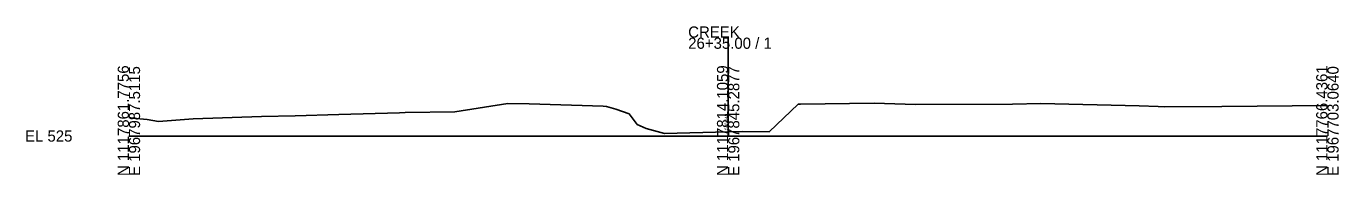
# Model space of a CAD drawing. Extents: x 9974 to 10303, y 9990 to 19550.
# Drawn here: x 9974.3 to 10302.8, y 15990.3 to 16027.5 of the extents above; entities that cross this region are included whole.
import ezdxf

# ---------------------------------------------------------------- set-up
doc = ezdxf.new("R2010")
doc.units = 0
for name, color, linetype in [('Level 10', 7, 'Continuous'), ('Level 60', 7, 'Continuous'), ('Level 63', 7, 'Continuous')]:
    doc.layers.add(name, color=color, linetype=linetype)

msp = doc.modelspace()

# ---------------------------------------------------------------- linework, layer by layer
at = {"layer": 'Level 60'}
for p, q in [((10081.57, 16006.09), (10094.84, 16008.14)), ((10094.84, 16008.14), (10100.16, 16008.06)), ((10100.16, 16008.06), (10118.7, 16007.45)), ((10118.7, 16007.45), (10119.51, 16007.42)), ((10119.51, 16007.42), (10121.91, 16006.75)), ((10121.91, 16006.75), (10125.23, 16005.56)), ((10160.27, 16001.03), (10167.54, 16007.95)), ((10167.54, 16007.95), (10168.11, 16007.96)), ((10168.11, 16007.96), (10186.51, 16008.21)), ((10186.51, 16008.21), (10196.87, 16007.9)), ((10196.87, 16007.9), (10221.21, 16007.98)), ((10221.21, 16007.98), (10228.26, 16008.15)), ((10228.26, 16008.15), (10252.85, 16007.53)), ((10252.85, 16007.53), (10257.66, 16007.36)), ((10257.66, 16007.36), (10259.1, 16007.33)), ((10259.1, 16007.33), (10273.54, 16007.4)), ((10273.54, 16007.4), (10300, 16007.61)), ((10000, 16004.6), (10000.99, 16004.51)), ((10000.99, 16004.51), (10004.6, 16004.14)), ((10004.6, 16004.14), (10007.43, 16003.62)), ((10007.43, 16003.62), (10016.1, 16004.32)), ((10016.1, 16004.32), (10033.23, 16004.85)), ((10033.23, 16004.85), (10041.66, 16005.09)), ((10041.66, 16005.09), (10052.51, 16005.42)), ((10052.51, 16005.42), (10067.71, 16005.84)), ((10067.71, 16005.84), (10069.15, 16005.91)), ((10069.15, 16005.91), (10081.57, 16006.09)), ((10125.23, 16005.56), (10127.2, 16002.85)), ((10127.2, 16002.85), (10129.49, 16001.88)), ((10129.49, 16001.88), (10134.1, 16000.62)), ((10134.1, 16000.62), (10150, 16001.05)), ((10150, 16001.05), (10153.59, 16001.15)), ((10153.59, 16001.15), (10160.27, 16001.03))]:
    msp.add_line(p, q, dxfattribs=at)
at = {"layer": 'Level 63'}
for p, q in [((10150, 16000), (10150, 16024.63)), ((10000, 16000), (10150, 16000)), ((10150, 16000), (10300, 16000))]:
    msp.add_line(p, q, dxfattribs=at)

# ---------------------------------------------------------------- texts
at = {"layer": 'Level 10'}
msp.add_text('526.049', height=0.8, rotation=90, dxfattribs=at).set_placement((10149.9, 16001.55))
at = {"layer": 'Level 63'}
for s, p in [('CREEK', (10140, 16024.63)), ('26+35.00 / 1', (10140, 16021.83)), ('EL 525', (9974, 15998.6))]:
    msp.add_text(s, height=2.8, dxfattribs=at).set_placement(p)
for s, p in [('N 1117861.7756', (10000, 15990)), ('E 1967987.5115', (10002.8, 15990)), ('N 1117814.1059', (10150, 15990)), ('E 1967845.2877', (10152.8, 15990)), ('N 1117766.4361', (10300, 15990)), ('E 1967703.0640', (10302.8, 15990))]:
    msp.add_text(s, height=2.8, rotation=90, dxfattribs=at).set_placement(p)

doc.saveas('drawing.dxf')
